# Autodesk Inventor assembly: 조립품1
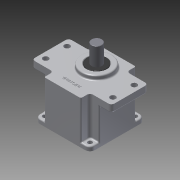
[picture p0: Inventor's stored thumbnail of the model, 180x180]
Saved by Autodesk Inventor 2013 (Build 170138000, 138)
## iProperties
Created: 2015-07
Part Number: 조립품1
Document SubType Name: Assembly
Designer: user
Author: user
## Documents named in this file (12)
- C:\Users\user\Desktop\450734V1028\조립품1.iam
- C:\Users\user\Desktop\450734V1028\메인축.ipt
- C:\Users\user\Desktop\450734V1028\서브축.ipt
- C:\Users\user\Desktop\450734V1028\베어링 608.ipt
- 베어링 608.ipt
- C:\Users\user\Desktop\450734V1028\베어링 6003.ipt
- 베어링 6003.ipt
- C:\Users\user\Desktop\450734V1028\커버.ipt
- C:\Users\user\Desktop\450734V1028\본체.ipt
- C:\Users\user\Desktop\450734V1028\오일실 8x22x7.ipt
- C:\Users\user\Desktop\450734V1028\오일실 17x32x8.ipt
- C:\Users\user\Desktop\450734V1028\M4x0.5x16.ipt
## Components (4 placed, 1 different names)
1. M4x0.5x12:1
2. M4x0.5x12:2
3. M4x0.5x12:3
4. M4x0.5x12:4
